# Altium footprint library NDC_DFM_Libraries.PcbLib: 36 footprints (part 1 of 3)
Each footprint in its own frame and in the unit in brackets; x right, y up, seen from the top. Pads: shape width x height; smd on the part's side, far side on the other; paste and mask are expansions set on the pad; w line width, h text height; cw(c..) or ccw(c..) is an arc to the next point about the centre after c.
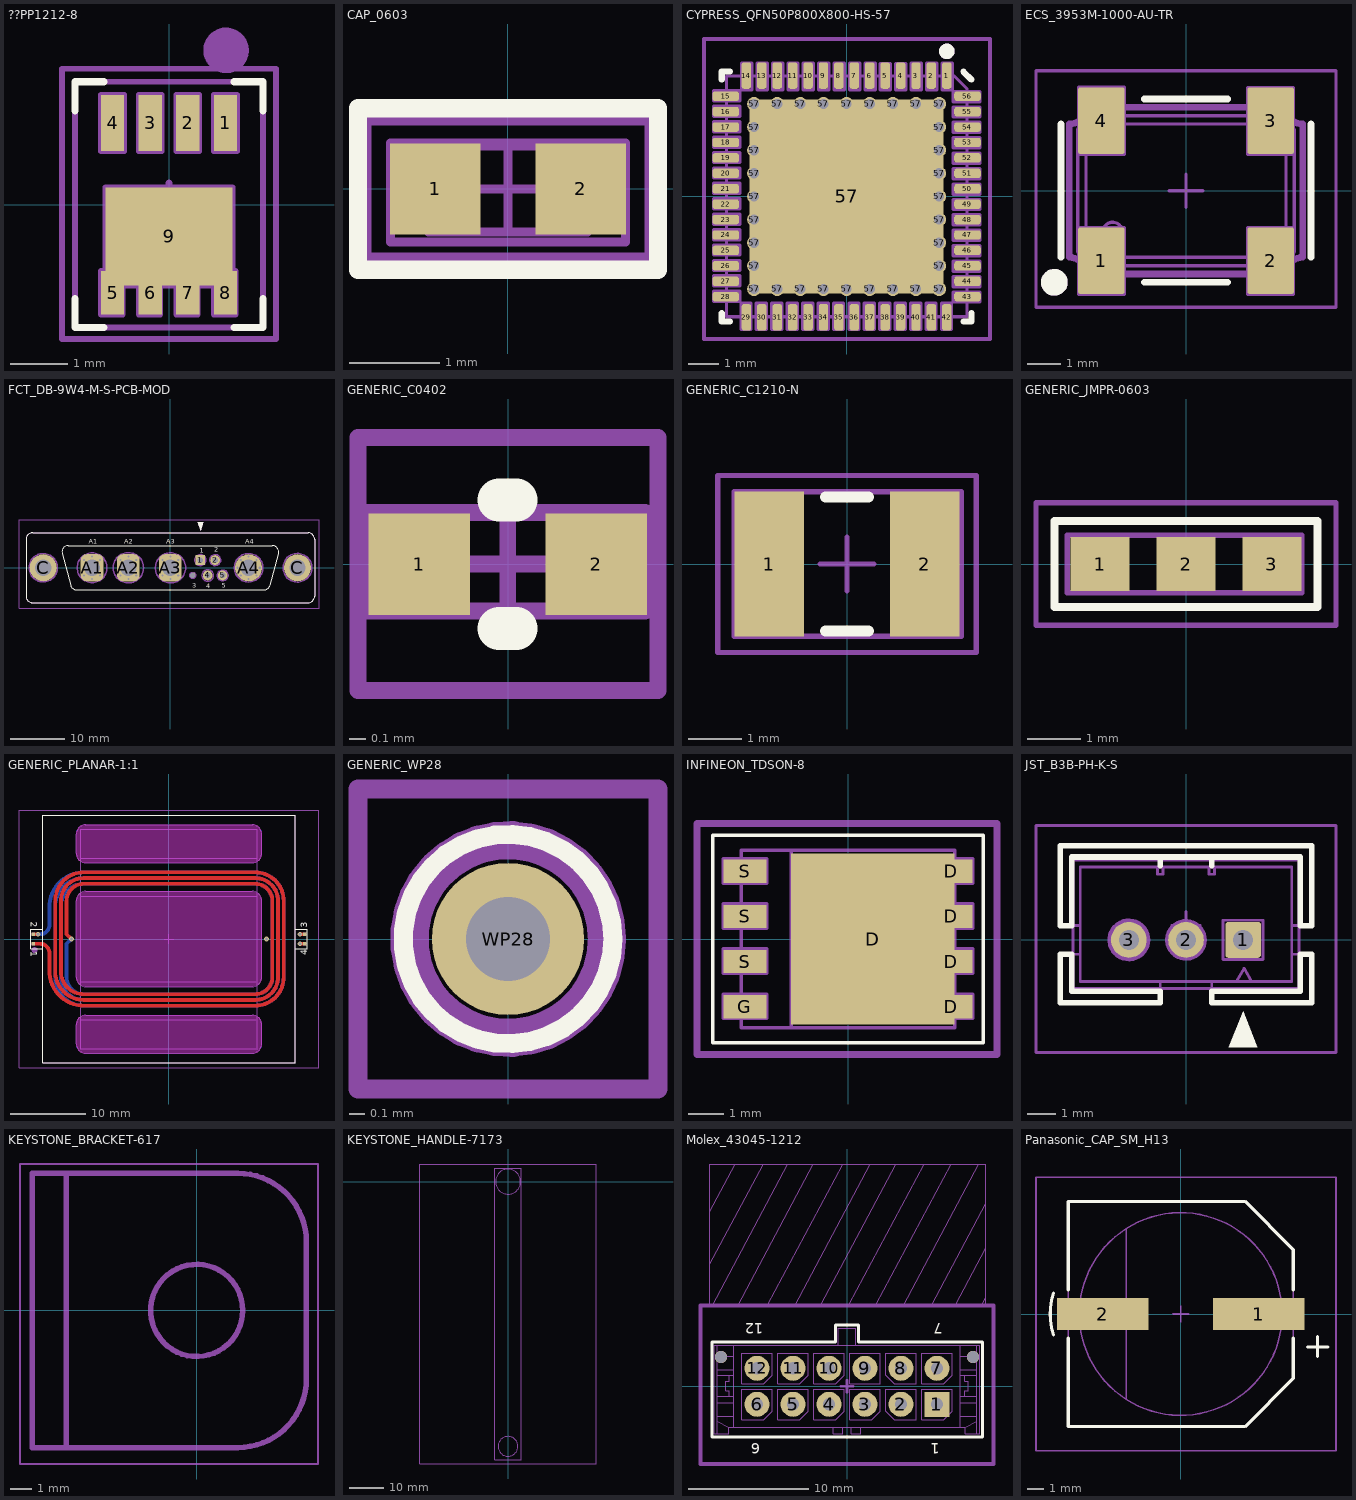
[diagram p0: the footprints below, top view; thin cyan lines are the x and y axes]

## ??PP1212-8 [mil]
height 44.09
pads (9):
  rect 16x39 smd mask+5: 1(39,56.5) 2(13,56.5) 3(-13,56.5) 4(-39,56.5)
  rect 16x30 smd mask+5: 5(-39,-61) 6(-13,-61) 7(13,-61) 8(39,-61)
  rect 88x68 smd: 9(0,-22)
Top Overlay:
  lines w5: -65,-65 -65,-85 -45,-85 ; -65,65 -65,85 -45,85 ; 45,-85 65,-85 65,-65 ; 45,85 65,85 65,65
M06 - ASSY TOP:
  circle w15.75: c39.49,106.73 r7.87
  lines w3.94: -65,-85 -65,85 65,85 65,-85 -65,-85 ; -47,-76 -47,-46 -32,-46 -32,-76 -47,-76 ; -47,37 -47,76 -31,76 -31,37 -47,37 ; -44,-56 -44,12 44,12 44,-56 -44,-56 ; -21,-76 -6,-76 -6,-46 -21,-46 -21,-76 ; -21,37 -5,37 -5,76 -21,76 -21,37 ; 5,-76 20,-76 20,-46 5,-46 5,-76 ; 5,37 21,37 21,76 5,76 5,37 ; 31,-76 46,-76 46,-46 31,-46 31,-76 ; 31,37 47,37 47,76 31,76 31,37
  text ".designator" at -60,15 h35
M15 - COURTYARD TOP:
  lines w3.94: -74,-93 74,-93 74,94 -74,94 -74,-93
  lines w5: -15,0 15,0 ; 0,-15 0,15
3D body: height 44.09, standoff 0, extent -66.93,-64.37 66.93,64.37

## CAP_0603 [mm] "Chip Capacitor, Body 1.6x0.8mm, IPC Medium Density"
height 0.85
pads (2):
  rect 1x1 smd: 1(-0.8,0) 2(0.8,0)
Top Overlay:
  lines w0.203: -1.651,-0.889 1.651,-0.889 1.651,0.889 -1.651,0.889 -1.651,-0.889
M06 - ASSY TOP:
  lines w0.1: -1.295,-0.584 -1.295,0.508 1.295,0.508 1.295,-0.584 -1.295,-0.584
  text ".designator" at -1.118,-0.406 h0.89
M13 - 3D TOP:
  lines w0.1: -0.875,-0.475 0.875,-0.475 0.875,0.475 -0.875,0.475 -0.875,-0.475
M15 - COURTYARD TOP:
  lines w0.1: -0.475,0 0.475,0 ; 0,-0.475 0,0.475 ; -1.55,-0.75 1.55,-0.75 1.55,0.75 -1.55,0.75 -1.55,-0.75
3D body: height 0.8, standoff 0, extent -0.8,-0.4 0.8,0.4

## CYPRESS_QFN50P800X800-HS-57 [mm] "Quad Flat No Lead; 56 Terminals; Body 8 x 8 mm; Pitch 0.5 mm, Punch Version"
height 1
pads (89):
  rrect50% 0.305x0.86 smd mask+0.051: 1(3.25,3.92) 14(-3.25,3.92) 29(-3.25,-3.92) 42(3.25,-3.92)
  rrect50% 0.305x0.86 smd mask+0.038: 2(2.75,3.92) 3(2.25,3.92) 4(1.75,3.92) 5(1.25,3.92) 6(0.75,3.92) 7(0.25,3.92) 8(-0.25,3.92) 9(-0.75,3.92) 10(-1.25,3.92) 11(-1.75,3.92) 12(-2.25,3.92) 13(-2.75,3.92) 30(-2.75,-3.92) 31(-2.25,-3.92) 32(-1.75,-3.92) 33(-1.25,-3.92) 34(-0.75,-3.92) 35(-0.25,-3.92) 36(0.25,-3.92) 37(0.75,-3.92) 38(1.25,-3.92) 39(1.75,-3.92) 40(2.25,-3.92) 41(2.75,-3.92)
  rrect50% 0.86x0.305 smd mask+0.051: 15(-3.92,3.25) 28(-3.92,-3.25) 43(3.92,-3.25) 56(3.92,3.25)
  rrect50% 0.86x0.305 smd mask+0.038: 16(-3.92,2.75) 17(-3.92,2.25) 18(-3.92,1.75) 19(-3.92,1.25) 20(-3.92,0.75) 21(-3.92,0.25) 22(-3.92,-0.25) 23(-3.92,-0.75) 24(-3.92,-1.25) 25(-3.92,-1.75) 26(-3.92,-2.25) 27(-3.92,-2.75) 44(3.92,-2.75) 45(3.92,-2.25) 46(3.92,-1.75) 47(3.92,-1.25) 48(3.92,-0.75) 49(3.92,-0.25) 50(3.92,0.25) 51(3.92,0.75) 52(3.92,1.25) 53(3.92,1.75) 54(3.92,2.25) 55(3.92,2.75)
  round 0.457 hole 0.33 mask+0.025: 57(-3,-3) 57(-3,-2.25) 57(-3,-1.5) 57(-3,-0.75) 57(-3,0) 57(-3,0.75) 57(-3,1.5) 57(-3,2.25) 57(-3,3) 57(-2.25,-3) 57(-2.25,3) 57(-1.5,-3) 57(-1.5,3) 57(-0.75,3) 57(-0.75,-3) 57(0,-3) 57(0,3) 57(0.75,-3) 57(0.75,3) 57(1.5,-3) 57(1.5,3) 57(2.25,3) 57(2.25,-3) 57(3,-1.5) 57(3,-0.75) 57(3,0) 57(3,0.75) 57(3,1.5) 57(3,2.25) 57(3,3) 57(3,-3) 57(3,-2.25)
  rect 6.3x6.3 smd mask-0.559: 57(0,0)
Top Overlay:
  circle w0.25: c3.25,4.705 r0.125
  lines w0.2: -4.05,-3.79 -4.05,-4.05 -3.79,-4.05 ; -4.05,3.79 -4.05,4.05 -3.79,4.05 ; 3.79,-4.05 4.05,-4.05 4.05,-3.79 ; 3.79,4.05 4.05,3.79
Top Paste:
  region: 2.54,2.54 -2.54,2.54 -2.54,-2.54 2.54,-2.54
M06 - ASSY TOP:
  drawing of 230 lines, arcs and shapes, not listed
  text ".designator" at -2.337,-0.61 h0.89
M15 - COURTYARD TOP:
  lines w0.127: -1.2,0 1.2,0 ; 0,-1.2 0,1.2 ; -4.623,-4.623 -4.623,5.105 4.648,5.105 4.648,-4.623 -4.623,-4.623
3D body: height 0.5, standoff 0, extent -3.659,-3.608 3.659,3.608
3D body: height 0.3, standoff 0.1, extent -1.403,-3.877 -1.142,-3.615
3D body: height 0.55, standoff 0, extent 2.392,2.371 3.076,3.055
3D body: height 0.2, standoff 0, extent 3.715,0.054 4.283,0.315
3D body: height 0.3, standoff 0.1, extent -0.411,-3.87 -0.15,-3.609
3D body: height 0.3, standoff 0.1, extent 1.091,-3.878 1.352,-3.617
3D body: height 0.2, standoff 0, extent -4.274,-1.405 -3.706,-1.144
3D body: height 0.2, standoff 0, extent 3.715,-3.432 4.283,-3.171
3D body: height 0.3, standoff 0.1, extent -0.88,3.537 -0.618,3.799
3D body: height 0.3, standoff 0.1, extent -3.873,-1.9 -3.612,-1.639
3D body: height 0.2, standoff 0, extent -4.274,-3.405 -3.706,-3.144
3D body: height 0.3, standoff 0.1, extent -3.409,-3.877 -3.147,-3.616
3D body: height 0.3, standoff 0.1, extent -3.873,-3.4 -3.612,-3.139
3D body: height 0.3, standoff 0.1, extent 1.62,3.537 1.882,3.799
3D body: height 0.3, standoff 0.1, extent 2.591,-3.878 2.852,-3.617
3D body: height 0.3, standoff 0.1, extent -2.909,-3.877 -2.647,-3.616
3D body: height 0.3, standoff 0.1, extent 0.12,3.537 0.382,3.799
3D body: height 0.2, standoff 0, extent -4.274,-0.405 -3.706,-0.144
3D body: height 0.2, standoff 0, extent 3.715,-1.932 4.283,-1.671
3D body: height 0.3, standoff 0.1, extent -3.873,-0.9 -3.612,-0.639
3D body: height 0.2, standoff 0, extent -2.885,3.632 -2.623,4.2
3D body: height 0.2, standoff 0, extent -4.274,0.595 -3.706,0.856
3D body: height 0.2, standoff 0, extent 3.115,-4.31 3.376,-3.742
3D body: height 0.3, standoff 0.1, extent 3.59,0.566 3.852,0.827
3D body: height 0.2, standoff 0, extent 3.719,-0.95 4.287,-0.689
3D body: height 0.3, standoff 0.1, extent 3.586,-0.432 3.848,-0.171
3D body: height 0.3, standoff 0.1, extent -3.38,3.537 -3.118,3.799
3D body: height 0.3, standoff 0.1, extent 3.344,3.064 3.857,3.326
3D body: height 0.3, standoff 0.1, extent -3.873,3.1 -3.612,3.361
3D body: height 0.3, standoff 0.1, extent 3.596,2.573 3.857,2.835
3D body: height 0.3, standoff 0.1, extent 3.59,1.594 3.852,1.855
3D body: height 0.3, standoff 0.1, extent -0.911,-3.87 -0.65,-3.609
3D body: height 0.2, standoff 0, extent 3.715,-2.932 4.283,-2.671
3D body: height 0.2, standoff 0, extent -2.385,3.632 -2.123,4.2
3D body: height 0.3, standoff 0.1, extent -3.873,1.1 -3.612,1.361
3D body: height 0.2, standoff 0, extent -1.409,-4.316 -1.148,-3.748
3D body: height 0.2, standoff 0, extent -4.274,0.095 -3.706,0.356
3D body: height 0.2, standoff 0, extent -4.274,-2.405 -3.706,-2.144
3D body: height 0.3, standoff 0.1, extent 1.12,3.537 1.382,3.799
3D body: height 0.2, standoff 0, extent -0.385,3.632 -0.123,4.2
3D body: height 0.3, standoff 0.1, extent 1.591,-3.878 1.852,-3.617
3D body: height 0.2, standoff 0, extent 3.737,3.06 4.306,3.321
3D body: height 0.2, standoff 0, extent 3.719,-1.442 4.287,-1.181
3D body: height 0.2, standoff 0, extent 0.583,-4.309 0.844,-3.741
3D body: height 0.3, standoff 0.1, extent -2.409,-3.877 -2.147,-3.616
3D body: height 0.2, standoff 0, extent 1.115,3.632 1.377,4.2
3D body: height 0.3, standoff 0.1, extent -3.873,1.6 -3.612,1.861
3D body: height 0.2, standoff 0, extent 3.723,1.588 4.291,1.849
3D body: height 0.3, standoff 0.1, extent -3.873,-2.9 -3.612,-2.639
3D body: height 0.2, standoff 0, extent 3.723,0.56 4.291,0.821
3D body: height 0.2, standoff 0, extent -4.274,2.095 -3.706,2.356
3D body: height 0.2, standoff 0, extent -1.914,-4.316 -1.653,-3.748
3D body: height 0.2, standoff 0, extent 0.115,3.632 0.377,4.2
3D body: height 0.2, standoff 0, extent 3.737,2.569 4.306,2.83
3D body: height 0.2, standoff 0, extent -1.885,3.632 -1.623,4.2
3D body: height 0.3, standoff 0.1, extent 0.589,-3.87 0.85,-3.609
3D body: height 0.2, standoff 0, extent -0.917,-4.309 -0.656,-3.741
3D body: height 0.3, standoff 0.1, extent 3.586,-1.436 3.848,-1.175
3D body: height 0.3, standoff 0.1, extent 2.091,-3.878 2.352,-3.617
3D body: height 0.3, standoff 0.1, extent -1.88,3.537 -1.618,3.799
3D body: height 0.2, standoff 0, extent -3.414,-4.316 -3.153,-3.748
3D body: height 0.3, standoff 0.1, extent -3.873,-1.4 -3.612,-1.139
3D body: height 0.3, standoff 0.1, extent -0.38,3.537 -0.118,3.799
3D body: height 0.3, standoff 0.1, extent -3.873,-0.4 -3.612,-0.139
3D body: height 0.2, standoff 0, extent -2.414,-4.316 -2.153,-3.748
3D body: height 0.2, standoff 0, extent -2.914,-4.316 -2.653,-3.748
3D body: height 0.2, standoff 0, extent 3.715,-2.432 4.283,-2.171
3D body: height 0.3, standoff 0.1, extent 3.582,0.06 3.844,0.321
3D body: height 0.3, standoff 0.1, extent 3.582,-1.926 3.844,-1.665
3D body: height 0.3, standoff 0.1, extent -2.38,3.537 -2.118,3.799
3D body: height 0.2, standoff 0, extent 0.615,3.632 0.877,4.2
3D body: height 0.3, standoff 0.1, extent 2.12,3.537 2.382,3.799
3D body: height 0.2, standoff 0, extent -3.385,3.632 -3.123,4.2
3D body: height 0.3, standoff 0.1, extent 0.089,-3.87 0.35,-3.609
3D body: height 0.3, standoff 0.1, extent -1.909,-3.877 -1.647,-3.616
3D body: height 0.3, standoff 0.1, extent -3.873,-2.4 -3.612,-2.139
3D body: height 0.3, standoff 0.1, extent 2.62,3.537 2.882,3.799
3D body: height 0.2, standoff 0, extent 3.723,2.072 4.291,2.333
3D body: height 0.3, standoff 0.1, extent 3.582,-2.926 3.844,-2.665
3D body: height 0.2, standoff 0, extent 2.085,-4.317 2.346,-3.749
3D body: height 0.3, standoff 0.1, extent -2.88,3.537 -2.618,3.799
3D body: height 0.2, standoff 0, extent 1.585,-4.317 1.846,-3.749
3D body: height 0.3, standoff 0.1, extent 3.12,3.537 3.382,3.799
3D body: height 0.2, standoff 0, extent 0.083,-4.309 0.344,-3.741
3D body: height 0.2, standoff 0, extent 1.085,-4.317 1.346,-3.749
3D body: height 0.3, standoff 0.1, extent 3.582,-2.426 3.844,-2.165
3D body: height 0.3, standoff 0.1, extent 3.59,1.094 3.852,1.355
3D body: height 0.3, standoff 0.1, extent -3.873,2.1 -3.612,2.361
3D body: height 0.2, standoff 0, extent 1.615,3.632 1.877,4.2
3D body: height 0.2, standoff 0, extent -4.274,1.595 -3.706,1.856
3D body: height 0.2, standoff 0, extent -4.274,1.095 -3.706,1.356
3D body: height 0.2, standoff 0, extent -0.885,3.632 -0.623,4.2
3D body: height 0.3, standoff 0.1, extent -3.873,0.6 -3.612,0.861
3D body: height 0.2, standoff 0, extent -4.274,2.595 -3.706,2.856
3D body: height 0.2, standoff 0, extent 2.615,3.632 2.877,4.2
3D body: height 0.3, standoff 0.1, extent -3.873,2.6 -3.612,2.861
3D body: height 0.3, standoff 0.1, extent -3.873,0.1 -3.612,0.361
3D body: height 0.2, standoff 0, extent -1.385,3.632 -1.123,4.2
3D body: height 0.3, standoff 0.1, extent 3.586,-0.945 3.848,-0.683
3D body: height 0.2, standoff 0, extent -4.274,-0.905 -3.706,-0.644
3D body: height 0.3, standoff 0.1, extent 3.582,-3.426 3.844,-3.165
3D body: height 0.2, standoff 0, extent -4.274,-2.905 -3.706,-2.644
3D body: height 0.3, standoff 0.1, extent 3.109,-3.885 3.37,-3.623
3D body: height 0.2, standoff 0, extent 3.115,3.632 3.377,4.2
3D body: height 0.2, standoff 0, extent 3.723,1.088 4.291,1.349
3D body: height 0.2, standoff 0, extent -4.274,3.095 -3.706,3.356
3D body: height 0.2, standoff 0, extent 2.585,-4.317 2.846,-3.749
3D body: height 0.3, standoff 0.1, extent -1.38,3.537 -1.118,3.799
3D body: height 0.2, standoff 0, extent 3.719,-0.438 4.287,-0.177
3D body: height 0.2, standoff 0, extent -0.417,-4.309 -0.156,-3.741
3D body: height 0.2, standoff 0, extent -4.274,-1.905 -3.706,-1.644
3D body: height 0.3, standoff 0.1, extent 0.62,3.537 0.882,3.799
3D body: height 0.3, standoff 0.1, extent 3.59,2.078 3.852,2.339
3D body: height 0.2, standoff 0, extent 2.115,3.632 2.377,4.2

## ECS_3953M-1000-AU-TR [mm] "SMD CLOCK OSCILLATOR"
height 1.7
pads (4):
  rrect10% 1.4x2 smd: 1(-2.54,-2.1) 2(2.54,-2.1) 3(2.54,2.1) 4(-2.54,2.1)
Top Overlay:
  circle w0.4: c-3.95,-2.75 r0.2
  lines w0.2: -3.75,-2 -3.75,2 ; -1.25,-2.75 1.25,-2.75 ; -1.25,2.75 1.25,2.75 ; 3.75,-2 3.75,2
M06 - ASSY TOP:
  circle w0.4: c-3.95,-2.75 r0.2
  lines w0.1: -3.226,-3.116 -1.854,-3.116 -1.854,-1.109 -3.226,-1.109 -3.226,-3.116 ; -3.226,1.084 -1.854,1.084 -1.854,3.091 -3.226,3.091 -3.226,1.084 ; -3.226,1.092 -3.226,3.099 -1.854,3.099 -1.854,1.092 -3.226,1.092 ; 1.854,-3.116 3.226,-3.116 3.226,-1.109 1.854,-1.109 1.854,-3.116 ; 1.854,1.084 3.226,1.084 3.226,3.091 1.854,3.091 1.854,1.084
  lines w0.2: -3.5,-2 cw(c-3.5,-2.5) -3,-2.5 3,-2.5 cw(c3.5,-2.5) 3.5,-2 3.5,2 cw(c3.5,2.5) 3,2.5 -3,2.5 cw(c-3.5,2.5) -3.5,2 -3.5,-2
  text ".designator" at -2.997,-0.686 h0.89
M13 - 3D TOP:
  circle w0.1: c-2.2,-1.25 r0.3
  lines w0.1: -3.5,-2 cw(c-3.5,-2.5) -3,-2.5 -2.74,-2.5 cw(c-2.54,-2.5) -2.34,-2.5 2.34,-2.5 cw(c2.54,-2.5) 2.74,-2.5 3,-2.5 cw(c3.5,-2.5) 3.5,-2 3.5,2 cw(c3.5,2.5) 3,2.5 2.74,2.5 cw(c2.54,2.5) 2.34,2.5 -2.34,2.5 cw(c-2.54,2.5) -2.74,2.5 -3,2.5 cw(c-3.5,2.5) -3.5,2 -3.5,-2 ; -3.25,-1.74 ccw(c-2.74,-1.74) -2.74,-2.25 2.34,-2.25 2.74,-2.25 ccw(c2.74,-1.74) 3.25,-1.74 3.25,1.74 ccw(c2.74,1.74) 2.74,2.25 -2.75,2.25 ccw(c-2.75,1.75) -3.25,1.75 -3.25,-1.74 ; -3,-1.75 ccw(c-2.75,-1.75) -2.75,-2 -1.75,-2 2.74,-2 ccw(c2.74,-1.74) 3,-1.74 3,1.75 ccw(c2.75,1.75) 2.75,2 -2.75,2 ccw(c-2.75,1.75) -3,1.75 -3,-1.75
M15 - COURTYARD TOP:
  lines w0.1: -0.5,0 0.5,0 ; 0,-0.5 0,0.5 ; -4.5,-3.5 -4.5,3.6 4.5,3.6 4.5,-3.5 -4.5,-3.5
3D body: height 1.7, standoff 0, extent -3.004,-2.005 3.005,2.004
3D body: height 1.71, standoff 0, extent -2.505,-1.555 -1.895,-0.945
3D body: height 1.4, standoff 0, extent -3.501,-2.501 3.501,2.501
3D body: height 1.6, standoff 0, extent -3.259,-2.259 3.259,2.259

## FCT_DB-9W4-M-S-PCB-MOD [mm] "FCT FM9W4P1-2464, Conn, DB, Mixed, 9 Pins, 4 Wide, Male, Straight, PCB Mt"
height 13.8
pads (11):
  rect 1.803x1.803 hole 1: 1(5.54,1.42)
  round 1.803 hole 1: 2(8.28,1.42) 4(6.91,-1.42) 5(9.68,-1.42)
  round 0.889 hole 1 unplated: 3(4.14,-1.42)
  rrect50% 4.2x5 / inner round 5 / far side rrect50% 4.2x5 hole 3: A1(-14.48,0) A2(-7.77,0) A3(0,0)
  round 5 hole 3: A4(14.48,0) C(-23.52,0) C(23.52,0)
via -14.48,2.063 diameter 0.813 hole 0.381
via -15.939,1.459 diameter 0.813 hole 0.381
via -13.021,1.459 diameter 0.813 hole 0.381
via -14.48,-2.063 diameter 0.813 hole 0.381
via -13.021,-1.459 diameter 0.813 hole 0.381
via -15.939,-1.459 diameter 0.813 hole 0.381
via -9.229,-1.459 diameter 0.813 hole 0.381
via -6.311,-1.459 diameter 0.813 hole 0.381
via -7.77,-2.063 diameter 0.813 hole 0.381
via -6.311,1.459 diameter 0.813 hole 0.381
via -9.229,1.459 diameter 0.813 hole 0.381
via -7.77,2.063 diameter 0.813 hole 0.381
via -1.459,-1.459 diameter 0.813 hole 0.381
via 1.459,-1.459 diameter 0.813 hole 0.381
via 0,-2.063 diameter 0.813 hole 0.381
via 1.459,1.459 diameter 0.813 hole 0.381
via -1.459,1.459 diameter 0.813 hole 0.381
via 0,2.063 diameter 0.813 hole 0.381
via 13.021,-1.459 diameter 0.813 hole 0.381
via 15.939,-1.459 diameter 0.813 hole 0.381
via 14.48,-2.063 diameter 0.813 hole 0.381
via 15.939,1.459 diameter 0.813 hole 0.381
via 13.021,1.459 diameter 0.813 hole 0.381
via 14.48,2.063 diameter 0.813 hole 0.381
via 12.417,0 diameter 0.813 hole 0.381
via 16.543,0 diameter 0.813 hole 0.381
Top Overlay:
  region: 5.588,6.858 5.08,8.382 6.096,8.382
  lines w0.127: -18.459,-3.211 ccw(c-17.3,-2.9) -17.3,-4.1 17.3,-4.1 ccw(c17.3,-2.9) 18.459,-3.211 ; -18.455,-3.21 -20.009,2.589 cw(c-18.85,2.9) -18.85,4.1 18.85,4.1 cw(c18.85,2.9) 20.009,2.589 18.455,-3.21 ; -26.7,-5.25 ccw(c-25.5,-5.25) -25.5,-6.45 25.5,-6.45 ccw(c25.5,-5.25) 26.7,-5.25 26.7,5.25 ccw(c25.5,5.25) 25.5,6.45 -25.5,6.45 ccw(c-25.5,5.25) -26.7,5.25 -26.7,-5.25
  text "A4" at 13.843,4.47 h0.89
  text "2" at 8.077,2.946 h0.89
  text "1" at 5.41,2.819 h0.89
  text "5" at 9.5,-3.734 h0.89
  text "3" at 4.013,-3.658 h0.89
  text "4" at 6.604,-3.785 h0.89
  text "A3" at -0.787,4.42 h0.89
  text "A2" at -8.56,4.47 h0.89
  text "A1" at -15.113,4.445 h0.89
M06 - ASSY TOP:
  circle w0.254: c23.52,0 r2.653
  circle w0.254: c14.48,0 r2.637
  circle w0.254: c9.68,-1.42 r1.002
  circle w0.254: c8.28,1.42 r1.014
  circle w0.254: c4.14,-1.42 r0.534
  circle w0.254: c6.91,-1.42 r1.069
  circle w0.254: c5.54,1.42 r1.038
  circle w0.254: c0.025,-0.024 r2.795
  circle w0.254: c-23.52,0 r2.62
  circle w0.254: c-7.77,0 r2.805
  circle w0.254: c-14.48,0 r2.753
  region: 5.588,6.858 5.08,8.382 6.096,8.382
  lines w0.127: -26.7,-5.25 ccw(c-25.5,-5.25) -25.5,-6.45 25.5,-6.45 ccw(c25.5,-5.25) 26.7,-5.25 26.7,5.25 ccw(c25.5,5.25) 25.5,6.45 -25.5,6.45 ccw(c-25.5,5.25) -26.7,5.25 -26.7,-5.25
  text ".designator" at -3.912,-5.588 h0.89
M15 - COURTYARD TOP:
  lines w0.127: -0.5,0 0,0 ; 0,-0.5 0,0 ; 0,0.5 0,0 ; 0.5,0 0,0
  lines w0.178: -28,-7.5 27.5,-7.5 27.5,8.89 -28,8.89 -28,-7.5
3D body: height 13.8, standoff -4.2, extent -26.474,-6.274 26.526,6.226

## GENERIC_C0402 [mm] "Chip Capacitor"
height 0.014
pads (2):
  rect 0.6x0.6 smd: 1(-0.527,-0.001) 2(0.523,-0.001)
Top Overlay:
  lines w0.254: -0.052,-0.382 0.049,-0.382 ; -0.052,0.38 0.049,0.38
M06 - ASSY TOP:
  lines w0.1: -0.838,-0.279 -0.838,0.305 0.813,0.305 0.813,-0.279 -0.838,-0.279
  text ".Designator" at -0.61,-0.076 h0.89
M15 - COURTYARD TOP:
  lines w0.1: -0.254,0 0.254,0 ; -0.002,-0.249 -0.002,0.249 ; -0.889,-0.75 0.889,-0.75 0.889,0.75 -0.889,0.75 -0.889,-0.75
3D body: height 0.4, standoff 0.05, extent 0.228,-0.301 0.571,0.299
3D body: height 0.4, standoff 0.05, extent -0.573,-0.302 -0.23,0.298
3D body: height 0.4, standoff 0.05, extent -0.234,-0.3 0.234,0.3

## GENERIC_C1210-N [mm] "Chip Capacitor, Body 3.2x2.5mm, IPC Medium Density"
height 1.5
pads (2):
  rect 1.3x2.7 smd: 1(-1.45,0) 2(1.45,0)
Top Overlay:
  lines w0.2: -0.4,-1.25 0.4,-1.25 ; -0.4,1.25 0.4,1.25
M06 - ASSY TOP:
  lines w0.1: -2.108,-1.35 -2.108,1.35 2.134,1.35 2.134,-1.35 -2.108,-1.35
  text ".designator" at -1.778,-0.737 h0.89
M15 - COURTYARD TOP:
  lines w0.1: -0.5,0 0.5,0 ; 0,-0.5 0,0.5 ; -2.413,-1.651 -2.413,1.651 2.413,1.651 2.413,-1.651 -2.413,-1.651
3D body: height 1.5, standoff 0, extent -1.7,-1.35 1.7,1.35

## GENERIC_JMPR-0603 [mm]
pads (3):
  rect 1.1x1 smd: 1(-1.6,0) 2(0,0) 3(1.6,0)
Top Overlay:
  lines w0.152: -2.45,-0.8 -2.45,0.8 2.45,0.8 2.45,-0.8 -2.45,-0.8
M06 - ASSY TOP:
  lines w0.1: -2.21,-0.533 -2.21,0.533 2.159,0.533 2.159,-0.533 -2.21,-0.533
  text ".designator" at -2.007,-0.305 h0.89
M15 - COURTYARD TOP:
  lines w0.1: -0.254,0 0.254,0 ; 0,-0.254 0,0.254 ; -2.794,-1.143 2.794,-1.143 2.794,1.143 -2.794,1.143 -2.794,-1.143
3D body: height 0.83, standoff -0.03, extent -1.6,-0.425 0,0.435

## GENERIC_PLANAR-1:1 [mil]
pads (4):
  rrect10% 20x20 smd paste-50 mask-50: 1(-712.5,-25) 2(-712.5,25) 3(712.5,25) 4(712.5,-25)
via 687.5,-25 diameter 25 hole 15
via 687.5,25 diameter 25 hole 15
via 512.5,0 diameter 25 hole 15
via -512.5,0 diameter 25 hole 15
via -687.5,25 diameter 25 hole 15
Top Layer:
  lines w20: -712.5,-25 -677.5,-25 cw(c-677.5,-75) -627.5,-75 -627.5,-170 ccw(c-447.5,-170) -447.5,-350 452.5,-350 ccw(c452.5,-200) 602.5,-200 602.5,200 ccw(c452.5,200) 452.5,350 -447.5,350 ccw(c-447.5,200) -597.5,200 -597.5,0 -597.5,-170 ccw(c-447.5,-170) -447.5,-320 452.5,-320 ccw(c452.5,-200) 572.5,-200 572.5,200 ccw(c452.5,200) 452.5,320 -447.5,320 ccw(c-447.5,200) -567.5,200 -567.5,0 -567.5,-170 ccw(c-447.5,-170) -447.5,-290 452.5,-290 ccw(c452.5,-200) 542.5,-200 542.5,200 ccw(c452.5,200) 452.5,290 -447.5,290 ccw(c-447.5,200) -537.5,200 -537.5,25 -512.5,0 ; -712.5,25 -687.5,25 ; 687.5,-25 712.5,-25 ; 687.5,25 712.5,25
Mid-Layer 1:
  lines w20: 512.5,0 537.5,-25 537.5,-200 cw(c447.5,-200) 447.5,-290 -452.5,-290 cw(c-452.5,-200) -542.5,-200 -542.5,200 cw(c-452.5,200) -452.5,290 447.5,290 cw(c447.5,170) 567.5,170 567.5,0 567.5,-200 cw(c447.5,-200) 447.5,-320 -452.5,-320 cw(c-452.5,-200) -572.5,-200 -572.5,200 cw(c-452.5,200) -452.5,320 447.5,320 cw(c447.5,170) 597.5,170 597.5,0 597.5,-200 cw(c447.5,-200) 447.5,-350 -452.5,-350 cw(c-452.5,-200) -602.5,-200 -602.5,200 cw(c-452.5,200) -452.5,350 447.5,350 cw(c447.5,170) 627.5,170 627.5,75 ccw(c677.5,75) 677.5,25 687.5,25
Mid-Layer 2:
  lines w20: 512.5,0 537.5,25 537.5,200 ccw(c447.5,200) 447.5,290 -452.5,290 ccw(c-452.5,200) -542.5,200 -542.5,-200 ccw(c-452.5,-200) -452.5,-290 447.5,-290 ccw(c447.5,-170) 567.5,-170 567.5,0 567.5,200 ccw(c447.5,200) 447.5,320 -452.5,320 ccw(c-452.5,200) -572.5,200 -572.5,-200 ccw(c-452.5,-200) -452.5,-320 447.5,-320 ccw(c447.5,-170) 597.5,-170 597.5,0 597.5,200 ccw(c447.5,200) 447.5,350 -452.5,350 ccw(c-452.5,200) -602.5,200 -602.5,-200 ccw(c-452.5,-200) -452.5,-350 447.5,-350 ccw(c447.5,-170) 627.5,-170 627.5,-75 cw(c677.5,-75) 677.5,-25 687.5,-25
Bottom Layer:
  lines w20: -687.5,25 -677.5,25 ccw(c-677.5,75) -627.5,75 -627.5,170 cw(c-447.5,170) -447.5,350 452.5,350 cw(c452.5,200) 602.5,200 602.5,-200 cw(c452.5,-200) 452.5,-350 -447.5,-350 cw(c-447.5,-200) -597.5,-200 -597.5,0 -597.5,170 cw(c-447.5,170) -447.5,320 452.5,320 cw(c452.5,200) 572.5,200 572.5,-200 cw(c452.5,-200) 452.5,-320 -447.5,-320 cw(c-447.5,-200) -567.5,-200 -567.5,0 -567.5,170 cw(c-447.5,170) -447.5,290 452.5,290 cw(c452.5,200) 542.5,200 542.5,-200 cw(c452.5,-200) 452.5,-290 -447.5,-290 cw(c-447.5,-200) -537.5,-200 -537.5,-25 -512.5,0
Top Overlay:
  lines w5: -662.5,-50 -725,-50 -725,50 -662.5,50 ; 662.5,-50 725,-50 725,50 662.5,50 ; -662.5,-650 662.5,-650 662.5,650 -662.5,650 -662.5,-650
  text "4" at 725,-85 h35
  text "3" at 725,60 h35
  text "1" at -725,-65 h35
  text "2" at -725,90 h35
Bottom Overlay:
  lines w5: -662.5,-650 -662.5,650 662.5,650 662.5,-650 -662.5,-650
Keep-Out Layer:
  board cut-out: -487.5,-550 -487.93,-450 -486.21,-436.95 -481.17,-424.78 -473.16,-414.34 -462.72,-406.32 -450.55,-401.29 -437.5,-399.57 -437.5,-400 437.5,-399.57 450.55,-401.29 462.72,-406.32 473.16,-414.34 481.18,-424.78 486.21,-436.95 487.93,-450 487.5,-450 487.93,-550 486.21,-563.05 481.18,-575.22 473.16,-585.66 462.72,-593.67 450.55,-598.71 437.5,-600.43 437.5,-600 -437.5,-600.43 -450.55,-598.71 -462.72,-593.67 -473.16,-585.66 -481.17,-575.22 -486.21,-563.05 -487.93,-550
  board cut-out: -487.5,450 -487.93,550 -486.21,563.05 -481.17,575.22 -473.16,585.66 -462.72,593.68 -450.55,598.71 -437.5,600.43 -437.5,600 437.5,600.43 450.55,598.71 462.72,593.68 473.16,585.66 481.18,575.22 486.21,563.05 487.93,550 487.5,550 487.93,450 486.21,436.95 481.18,424.78 473.16,414.34 462.72,406.33 450.55,401.29 437.5,399.57 437.5,400 -437.5,399.57 -450.55,401.29 -462.72,406.33 -473.16,414.34 -481.17,424.78 -486.21,436.95 -487.93,450
  board cut-out: -487.5,-200 -487.93,200 -486.21,213.05 -481.17,225.22 -473.16,235.66 -462.72,243.68 -450.55,248.71 -437.5,250.43 -437.5,250 437.5,250.43 450.55,248.71 462.72,243.68 473.16,235.66 481.18,225.22 486.21,213.05 487.93,200 487.5,200 487.93,-200 486.21,-213.05 481.18,-225.22 473.16,-235.66 462.72,-243.67 450.55,-248.71 437.5,-250.43 437.5,-250 -437.5,-250.43 -450.55,-248.71 -462.72,-243.67 -473.16,-235.66 -481.17,-225.22 -486.21,-213.05 -487.93,-200
M01 - BOARD OUTLINE:
  lines w5: -487.5,-550 ccw(c-437.5,-550) -437.5,-600 437.5,-600 ccw(c437.5,-550) 487.5,-550 487.5,-450 ccw(c437.5,-450) 437.5,-400 -437.5,-400 ccw(c-437.5,-450) -487.5,-450 -487.5,-550 ; -487.5,-200 ccw(c-437.5,-200) -437.5,-250 437.5,-250 ccw(c437.5,-200) 487.5,-200 487.5,200 ccw(c437.5,200) 437.5,250 -137.5,250 -437.5,250 ccw(c-437.5,200) -487.5,200 -487.5,-200 ; -487.5,450 ccw(c-437.5,450) -437.5,400 437.5,400 ccw(c437.5,450) 487.5,450 487.5,550 ccw(c437.5,550) 437.5,600 -437.5,600 ccw(c-437.5,550) -487.5,550 -487.5,450
M06 - ASSY TOP:
  circle w15.75: c-705.51,-58.27 r7.87
  lines w5: -462.5,-425 -462.5,-225 ; -462.5,-425 -462.5,-575 457.5,-575 462.5,-575 462.5,-425 ; -462.5,-425 462.5,-425 ; -462.5,-225 -462.5,225 ; -462.5,-225 462.5,-225 ; -462.5,225 -462.5,425 ; -462.5,225 462.5,225 ; -462.5,425 -462.5,575 462.5,575 462.5,425 ; -462.5,425 462.5,425 ; 462.5,-425 462.5,-225 ; 462.5,-225 462.5,225 ; 462.5,225 462.5,425 ; -662.5,-650 662.5,-650 662.5,650 -662.5,650 -662.5,-650 ; -487.5,-550 ccw(c-437.5,-550) -437.5,-600 437.5,-600 ccw(c437.5,-550) 487.5,-550 487.5,-450 ccw(c437.5,-450) 437.5,-400 -437.5,-400 ccw(c-437.5,-450) -487.5,-450 -487.5,-550 ; -487.5,-200 ccw(c-437.5,-200) -437.5,-250 437.5,-250 ccw(c437.5,-200) 487.5,-200 487.5,200 ccw(c437.5,200) 437.5,250 -137.5,250 -437.5,250 ccw(c-437.5,200) -487.5,200 -487.5,-200 ; -487.5,450 ccw(c-437.5,450) -437.5,400 437.5,400 ccw(c437.5,450) 487.5,450 487.5,550 ccw(c437.5,550) 437.5,600 -437.5,600 ccw(c-437.5,550) -487.5,550 -487.5,450 ; -452.5,-350 447.5,-350 -452.5,-350 ; -452.5,-320 447.5,-320 -452.5,-320 ; -452.5,-290 447.5,-290 -452.5,-290 ; -452.5,290 447.5,290 -452.5,290 ; -452.5,320 447.5,320 -452.5,320 ; -452.5,350 447.5,350 -452.5,350 ; -447.5,-350 452.5,-350 -447.5,-350 ; -447.5,-320 452.5,-320 -447.5,-320 ; -447.5,-290 452.5,-290 -447.5,-290 ; -447.5,290 452.5,290 -447.5,290 ; -447.5,320 452.5,320 -447.5,320 ; -447.5,350 452.5,350 -447.5,350
  text ".designator" at -172,-117 h35
M15 - COURTYARD TOP:
  lines w5: -25,0 25,0 ; 0,-25 0,25 ; -787.5,-675 787.5,-675 787.5,675 -787.5,675 -787.5,-675
3D body: height 70, standoff 20, extent -462.5,-575 462.5,575
3D body: height 20, standoff -83, extent -462.5,-225 462.5,225
3D body: height 20, standoff -83, extent -462.5,-575 462.5,-425
3D body: height 20, standoff -83, extent -462.5,425 462.5,575
3D body: height -83, standoff -133, extent -462.5,-575 462.5,575

## GENERIC_WP28 [mil] "PAD,WIRE,28AWG,TH"
pads (1):
  round 40 hole 22: WP28(0,0)
Top Overlay:
  circle w5: c0,0 r27.5
M06 - ASSY TOP:
  circle w3.94: c0,0 r27
  circle w10: c0.06,0 r25.95
  text ".designator" at -39,-60 h35
M15 - COURTYARD TOP:
  lines w5: -11.81,0 11.81,0 ; 0.06,-12.27 0.06,12.28 ; -39.37,-39.37 39.37,-39.37 39.37,39.37 -39.37,39.37 -39.37,-39.37
3D body: height 258, standoff 8, extent -12.2,-12.27 12.31,12.28
3D body: height 50, standoff -80, extent -6.25,-6.28 6.3,6.29

## INFINEON_TDSON-8 [mm] "INFINEON  SuperS08 125W"
height 1.1
pads (9):
  rect 4.6x4.8 smd: D(0.7,0)
  rect 1.2x0.65 smd: D(2.9,-1.905) D(2.9,-0.635) D(2.9,0.635) D(2.9,1.905) G(-2.9,-1.905) S(-2.9,-0.635) S(-2.9,0.635) S(-2.9,1.905)
Top Overlay:
  lines w0.1: -3.81,-2.921 -3.81,2.921 3.81,2.921 3.81,-2.921 -3.81,-2.921
M06 - ASSY TOP:
  lines w0.1: -1.6,-2.5 -1.6,2.5 ; -3.505,-2.235 -3.505,-1.549 -2.286,-1.549 -2.286,-2.235 -3.505,-2.235 ; -3.505,-0.965 -3.505,-0.279 -2.286,-0.279 -2.286,-0.965 -3.505,-0.965 ; -3.505,0.305 -3.505,0.991 -2.286,0.991 -2.286,0.305 -3.505,0.305 ; -3.505,1.575 -2.286,1.575 -2.286,2.261 -3.505,2.261 -3.505,1.575 ; -3,-2.5 -3,2.5 3,2.5 3,-2.5 -3,-2.5 ; 2.295,-2.235 2.295,-1.549 3.514,-1.549 3.514,-2.235 2.295,-2.235 ; 2.295,-0.965 2.295,-0.279 3.514,-0.279 3.514,-0.965 2.295,-0.965 ; 2.295,0.305 2.295,0.991 3.514,0.991 3.514,0.305 2.295,0.305 ; 2.295,1.575 2.295,2.261 3.514,2.261 3.514,1.575 2.295,1.575
  text ".designator" at -1.245,-1.295 h0.89
M15 - COURTYARD TOP:
  lines w0.2: -0.5,0 0.5,0 ; 0,-0.5 0,0.5 ; -4.25,-3.25 -4.25,3.25 4.191,3.25 4.191,-3.25 -4.25,-3.25
3D body: height 1.12, standoff 0, extent -3.12,-2.625 3.12,2.625

## JST_B3B-PH-K-S [mm]
pads (3):
  rrect15% 1.25x1.25 hole 0.7: 1(2,0)
  round 1.25 hole 0.7: 2(0,0) 3(-2,0)
Top Overlay:
  region: 2,-2.5 1.5,-3.75 2.5,-3.75
  lines w0.2: -0.9,2.6 -0.9,2.8 ; 0.9,2.6 0.9,2.9 ; -4.4,-2.2 -4.4,-0.5 -4,-0.5 -4,-1.8 -0.9,-1.8 -0.9,-2.2 -4.4,-2.2 ; -4.4,0.5 -4.4,3.3 4.4,3.3 4.4,0.5 4,0.5 4,2.9 -4,2.9 -4,0.5 -4.4,0.5 ; 0.9,-2.2 4.4,-2.2 4.4,-0.5 4,-0.5 4,-1.8 0.9,-1.8 0.9,-2.2
M06 - ASSY TOP:
  circle w0.254: c0,0 r0.602
  circle w0.254: c-2,0 r0.624
  lines w0.1: -3.95,-0.5 -3.7,-0.5 ; -3.95,0.5 -3.7,0.5 ; -1,2.55 -1,2.3 -0.8,2.3 -0.8,2.55 ; -0.9,-1.7 -0.9,-1.45 ; 0.8,2.55 0.8,2.3 1,2.3 1,2.55 ; 0.9,-1.7 0.9,-1.45 ; 1.782,-1.441 2.032,-0.991 2.282,-1.441 ; 3.7,-0.5 3.95,-0.5 ; 3.7,0.5 3.95,0.5 ; -3.95,-1.7 3.95,-1.7 3.95,2.8 -3.95,2.8 -3.95,-1.7 ; -3.7,-1.45 -3.7,2.55 3.7,2.55 3.7,-1.45 -3.7,-1.45 ; 1.295,-0.686 2.692,-0.686 2.692,0.686 1.295,0.686 1.295,-0.686
  text ".designator" at -3.251,1.067 h0.89
M15 - COURTYARD TOP:
  lines w0.1: -0.5,0.5 0.5,0.5 ; 0,0 0,1 ; -5.25,-3.937 5.25,-3.937 5.25,4 -5.25,4 -5.25,-3.937
3D body: height 6, standoff -3.4, extent -3.95,-1.7 3.95,2.8

## KEYSTONE_BRACKET-617 [mm] "BRACKET,RIGHT-ANGL,THRD,6-32 (STEEL)"
height 14.68
M06 - ASSY TOP:
  circle w0.254: c0,0 r2.134
  lines w0.254: -6.045,-6.35 -6.045,6.35 ; -7.62,-6.35 -7.62,6.35 1.905,6.35 cw(c1.905,3.175) 5.08,3.175 5.08,-3.175 cw(c1.905,-3.175) 1.905,-6.35 -7.62,-6.35
  text ".designator" at -5.029,-4.14 h0.89
M15 - COURTYARD TOP:
  lines w0.1: -8.179,-7.112 -8.179,6.782 5.613,6.782 5.613,-7.112 -8.179,-7.112
3D body: height 14.68, standoff 0, extent -7.594,-6.35 5.106,6.35

## KEYSTONE_HANDLE-7173 [mm] "HANDLE,ALUM,BLK,3.00\",8-32"
height 11.049
M06 - ASSY TOP:
  circle w0.1: c0,-76.2 r2.84
  circle w0.1: c0,0 r3.592
  lines w0.1: -3.81,-80.01 -3.81,3.81 3.81,3.81 3.81,-80.01 -3.81,-80.01
  text ".designator" at 0.508,-46.838 h0.89
M15 - COURTYARD TOP:
  lines w0.1: -25.4,-81.28 25.4,-81.28 25.4,5.08 -25.4,5.08 -25.4,-81.28
3D body: height 46.43, standoff 8.33, extent -3.175,-79.375 3.175,3.175

## Molex_43045-1212 [mm] "Header, 12 Position, Pitch 3.0mm, Body 21.65 mm L X 7.37mm W, Height 9.91mm"
height 9.906
pads (14):
  rect 2.083x2.083 / inner oval 1.4x2.4 / far side rect 2.083x2.083 hole 1.02 mask+0.051: 1(7.5,-1.5)
  round 2.083 / inner oval 1.4x2.4 / far side round 2.083 hole 1.02 mask+0.051: 2(4.5,-1.5) 3(1.5,-1.5) 4(-1.5,-1.5) 5(-4.5,-1.5) 6(-7.5,-1.5)
  round 2.083 hole 1.02 mask+0.051: 7(7.5,1.5) 8(4.5,1.5) 9(1.5,1.5) 10(-1.5,1.5) 11(-4.5,1.5) 12(-7.5,1.5)
  round 1.016 hole 1.02 unplated: MNT(-10.5,2.44) MNT(10.5,2.44)
Top Overlay:
  lines w0.254: -11.252,-4.216 -11.252,3.675 -0.975,3.675 -0.975,5.1 0.975,5.1 0.975,3.675 11.303,3.675 11.303,-4.216 -11.252,-4.216
  text "7" at 8,5.25 h0.89
  text "12" at -7,5.25 h0.89
  text "6" at -7.25,-4.75 h0.89
  text "1" at 7.75,-4.75 h0.89
M06 - ASSY TOP:
  lines w0.102: -10.825,-3.945 -10.825,3.425 ; -10.825,-2.935 -9.875,-3.435 ; -10.825,-2.505 -9.425,-2.505 ; -10.825,-1.38 -9.425,-1.38 ; -10.825,-0.85 -9.425,-0.85 ; -10.825,0.9 -9.425,0.9 ; -10.825,1.37 -9.425,1.37 ; -10.825,2.495 -9.425,2.495 ; -9.825,-0.85 -9.825,-0.375 -10.125,-0.375 -10.125,0.425 -9.825,0.425 -9.825,0.9 ; -9.425,-3.435 -9.425,3.425 ; -1.15,-3.435 -1.15,-3.945 -0.35,-3.945 -0.35,-3.435 ; -0.75,3.425 -0.75,4.825 0.75,4.825 0.75,3.425 ; 0.35,-3.435 0.35,-3.945 1.15,-3.945 1.15,-3.435 ; 9.425,-3.435 9.425,3.425 ; 9.425,-2.505 10.825,-2.505 ; 9.425,-1.38 10.825,-1.38 ; 9.425,-0.85 10.825,-0.85 ; 9.425,0.9 10.825,0.9 ; 9.425,1.37 10.825,1.37 ; 9.425,2.495 10.825,2.495 ; 9.825,-0.85 9.825,-0.375 10.125,-0.375 10.125,0.425 9.825,0.425 9.825,0.9 ; 10.825,-3.945 10.825,3.425 ; 10.825,-2.935 9.875,-3.435 ; -9.875,-3.435 -9.875,-3.945 -11.075,-3.945 -11.075,3.425 11.075,3.425 11.075,-3.945 9.875,-3.945 9.875,-3.435 ; -9.875,-3.435 9.875,-3.435 ; -8.77,-2.775 -6.93,-2.775 -6.23,-2.075 -6.23,-0.235 -8.77,-0.235 -8.77,-2.775 ; -8.77,0.225 -8.77,2.765 -6.23,2.765 -6.23,0.925 -6.93,0.225 -8.77,0.225 ; -5.77,-2.775 -5.77,-0.235 -3.23,-0.235 -3.23,-2.075 -3.93,-2.775 -5.77,-2.775 ; -5.77,0.225 -5.77,2.765 -3.23,2.765 -3.23,0.925 -3.93,0.225 -5.77,0.225 ; -2.77,-2.775 -2.77,-0.235 -0.23,-0.235 -0.23,-2.075 -0.93,-2.775 -2.77,-2.775 ; -2.77,0.225 -2.77,2.765 -0.23,2.765 -0.23,0.925 -0.93,0.225 -2.77,0.225 ; 0.23,-2.775 2.07,-2.775 2.77,-2.075 2.77,-0.235 0.23,-0.235 0.23,-2.775 ; 0.23,0.225 0.23,2.765 2.77,2.765 2.77,0.225 0.23,0.225 ; 3.23,-2.075 3.23,-0.235 5.77,-0.235 5.77,-2.775 3.93,-2.775 3.23,-2.075 ; 3.23,0.925 3.23,2.765 5.77,2.765 5.77,0.225 3.93,0.225 3.23,0.925 ; 6.23,-2.775 8.07,-2.775 8.77,-2.075 8.77,-0.235 6.23,-0.235 6.23,-2.775 ; 6.23,0.225 8.07,0.225 8.77,0.925 8.77,2.765 6.23,2.765 6.23,0.225
  text "1" at 8.8,-3.2 h0.89
  text ".designator" at -3.658,-5.842 h0.89
M15 - COURTYARD TOP:
  lines w0.102: -11.425,14.525 -9.293,18.523 ; -11.418,10.185 -6.997,18.474 ; -11.198,6.737 -4.925,18.5 ; -9.082,6.767 -2.825,18.5 ; -6.601,6.801 -0.375,18.475 ; -4.332,6.767 1.925,18.5 ; -2.135,6.831 4.075,18.475 ; 0.194,6.817 6.425,18.5 ; 2.444,6.817 8.675,18.5 ; 4.732,6.773 11,18.525 ; 7.107,6.823 11.575,15.2 ; 9.053,6.787 11.569,11.503 ; 11.249,6.764 11.575,7.375 ; 11.575,6.75 0.075,6.75 -11.425,6.75 -11.425,18.5 0.075,18.5 11.575,18.5 11.575,6.775
  lines w0.229: -0.508,0 0.508,0 ; 0,-0.508 0,0.508
  lines w0.33: -12.192,-6.477 12.192,-6.477 12.192,6.75 -12.192,6.75 -12.192,-6.477
  text "THUMB" at -3.275,13.15 h0.89
  text "CLEARANCE" at -6.125,10.475 h0.89
3D body: height 25, standoff 11, extent -9.293,-4.394 9.557,6.456
3D body: height 9.91, standoff -3.18, extent -11.075,-3.97 11.075,4.8

## Panasonic_CAP_SM_H13 [mm]
height 13.5
pads (2):
  rect 5.7x2 smd: 1(4.85,0) 2(-4.85,0)
Top Overlay:
  lines w0.2: -7.909,-1.303 cw(c-3.9,0) -7.909,1.303 ; -7,-1.5 -7,-7 4,-7 7,-4 7,-1.5 ; -7,1.5 -7,7 4,7 7,4 7,1.5 ; 7.9,-2.05 9.15,-2.05 ; 8.5,-2.65 8.5,-1.4
M06 - ASSY TOP:
  circle w0.1: c0,0 r6.3
  lines w0.1: -3.4,-5.3 -3.4,5.3 ; -7,-7 -7,7 4,7 7,4 7,-4 4,-7 -7,-7
  text ".designator" at -1.575,-0.457 h0.89
M15 - COURTYARD TOP:
  lines w0.1: -0.5,0 0.5,0 ; 0,-0.5 0,0.5 ; -9,-8.5 9.652,-8.5 9.652,8.5 -9,8.5 -9,-8.5
3D body: height 13.5, standoff -0.01, extent -6.9,-6.75 6.9,6.75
